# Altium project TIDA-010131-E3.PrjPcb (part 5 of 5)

## Sheet TIDA-010131-E3_Hardware.SchDoc
size 431 x 279 mm; Date: Not shown in title block; ApprovedBy: Not shown in title block; CheckedBy: Not shown in title block; Author: Not shown in title block; CompanyName: Not shown in title block; DrawnBy: Avinash N; Engineer: Not shown in title block; Organization: Not shown in title block; Address1: Not shown in title block; Address2: Not shown in title block; Address3: Not shown in title block; Address4: Not shown in title block; DocumentNumber: 1; Revision: Use project parameter SCH_Rev; SheetNumber: 9; SheetTotal: 9; PageSetup: Record=PageOptions¦CenterHorizontal=True¦CenterVertical=True¦PrintScale=1.00¦XCorrection=1.00¦YCorrection=1.00¦PrintKind=0¦BorderSize=5000000¦LeftOffset=0¦BottomOffset=0¦Orientation=2¦PaperLength=1000¦PaperWidth=1000¦Scale=100¦PaperSource=15¦PrintQuality=600¦MediaType=1¦DitherType=10¦PaperKind=Letter¦PrintScaleMode=1
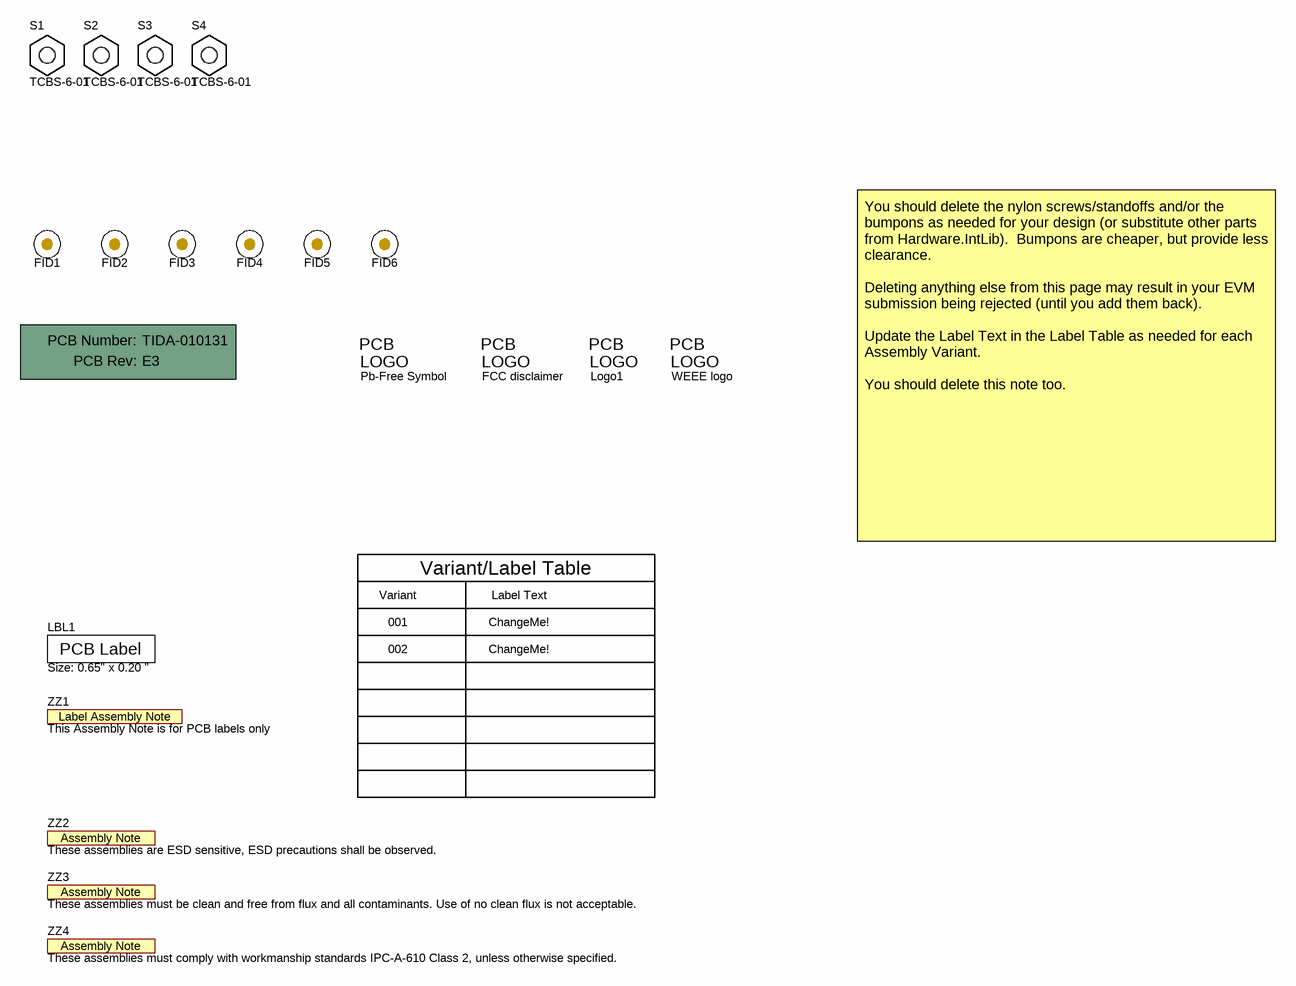
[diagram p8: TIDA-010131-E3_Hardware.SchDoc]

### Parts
!PCB1  Printed Circuit Board  (value not drawn)  (mechanical)
FID1  Fiducial  [Fiducial10-20]  (value not drawn)
FID2  Fiducial  [Fiducial10-20]  (value not drawn)
FID3  Fiducial  [Fiducial10-20]  (value not drawn)
FID4  Fiducial  [Fiducial10-20]  (value not drawn)
FID5  Fiducial  [Fiducial10-20]  (value not drawn)
FID6  Fiducial  [Fiducial10-20]  (value not drawn)
LBL1  Size: 0.65" x 0.20 "  [Label_650x200]
Logo1  ESD Susceptible  [ESD_Overlay_SMALL]  (value not drawn)  (no BOM)
Logo2  Pb-Free Symbol  [Pb-Free_Overlay_Small]  (no BOM)
Logo3  FCC disclaimer  [FCC_disclaimer]  (no BOM)
Logo4  WEEE logo  [WEEE_Minimum]  (no BOM)
S1  TCBS-6-01  [TCBS-6-01]
S2  TCBS-6-01  [TCBS-6-01]
S3  TCBS-6-01  [TCBS-6-01]
S4  TCBS-6-01  [TCBS-6-01]
ZZ1  This Assembly Note is for PCB labels only  [AssemblyNoteLabel]  (no BOM)
ZZ2  These assemblies are ESD sensitive, ESD precautions shall be observed.  [AssemblyNote]  (no BOM)
ZZ3  These assemblies must be clean and free from flux and all contaminants. Use of no clean flux is not acceptable.  [AssemblyNote]  (no BOM)
ZZ4  These assemblies must comply with workmanship standards IPC-A-610 Class 2, unless otherwise specified.  [AssemblyNote]  (no BOM)

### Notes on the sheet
- Variant
- Variant/Label Table
- Label Text
- You should delete the nylon screws/standoffs and/or the bumpons as needed for your design (or substitute other parts from Hardware.IntLib).  Bumpons are cheaper, but provide less clearance.
  Deleting anything else from this page may result in your EVM submission being rejected (until you add them back).
  Update the Label Text in the Label Table as needed for each Assembly Variant.
  You should delete this note too.
- 001
- 002
- ChangeMe!

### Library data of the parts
!PCB1 = PCB: Manufacturer: Any; PartNumber: TIDA-010131; SymbolCreator: a0412235
FID1-FID6 = Fiducial: Fiducial mark.  There is nothing to buy or mount.; SymbolCreator: codlsc
LBL1 = THT-14-423-10: Thermal Transfer Printable Labels, 0.650" W x 0.200" H - 10,000 per roll; Manufacturer: Brady; SymbolCreator: a0412235; CompType: Label
Logo1 = ESD_Susceptible: ESD Susceptible Symbol; SymbolCreator: a0412235
Logo2 = Pb-Free: SymbolCreator: a0412235
Logo3 = FCC_disclaimer: SymbolCreator: codlsc
Logo4 = CMP-0074769-1
S1-S4 = TCBS-6-01: HEX STANDOFF SPACER, 9.53 mm; Manufacturer: Richco Plastics; SymbolCreator: a0412235
ZZ1 = AssemblyNoteLabel: SymbolCreator: a0412235
ZZ2-ZZ4 = AssemblyNote: SymbolCreator: codlsc

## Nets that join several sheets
+2.5V: TIDA-010131-E3_LMK0482x _CLK_PWR (9 pins), TIDA-010131-E3_POWER SUPPLIES (7 pins)
+3.3V_LMX: TIDA-010131-E3_LMX2594R_1 (11 pins), TIDA-010131-E3_LMX2594R_2 (11 pins), TIDA-010131-E3_POWER SUPPLIES (7 pins)
+3.3V_LMXRF: TIDA-010131-E3_LMX2594R_1 (L11.1 L12.1 R87.1), TIDA-010131-E3_LMX2594R_2 (L13.1 L14.1 R120.1), TIDA-010131-E3_POWER SUPPLIES (7 pins)
+3.3V_VCO: TIDA-010131-E3_LMK0482x (5 pins), TIDA-010131-E3_POWER SUPPLIES (8 pins)
+3.3VLMK: TIDA-010131-E3_LMK0482x (8 pins), TIDA-010131-E3_LMK0482x _CLK_PWR (7 pins), TIDA-010131-E3_LMK00304_Buffer (14 pins), TIDA-010131-E3_LMX2594R_1 (C192.2 U23.8), TIDA-010131-E3_LMX2594R_2 (C193.2 U24.8), TIDA-010131-E3_POWER SUPPLIES (12 pins)
GND: TIDA-010131-E3_LMK0482x (98 pins), TIDA-010131-E3_LMK0482x _CLK_PWR (128 pins), TIDA-010131-E3_LMK00304_Buffer (28 pins), TIDA-010131-E3_LMX2594R_1 (63 pins), TIDA-010131-E3_LMX2594R_2 (63 pins), TIDA-010131-E3_USB (53 pins), TIDA-010131-E3_POWER SUPPLIES (99 pins)
Vcc1_VCO: TIDA-010131-E3_LMK0482x (U1.10 U1.33 U1.36), TIDA-010131-E3_LMK0482x _CLK_PWR (C34.1 C35.1 C36.1 L7.2)
Vcc2_CG1: TIDA-010131-E3_LMK0482x (U1.17), TIDA-010131-E3_LMK0482x _CLK_PWR (C26.1 L1.2)
Vcc3_SYSREF: TIDA-010131-E3_LMK0482x (U1.21), TIDA-010131-E3_LMK0482x _CLK_PWR (C28.1 L2.2)
Vcc4_CG2: TIDA-010131-E3_LMK0482x (U1.26), TIDA-010131-E3_LMK0482x _CLK_PWR (C31.1 L3.2)
Vcc7_OSCout: TIDA-010131-E3_LMK0482x (U1.39), TIDA-010131-E3_LMK0482x _CLK_PWR (C189.1 L6.2)
Vcc8_OSCin: TIDA-010131-E3_LMK0482x (U1.42), TIDA-010131-E3_LMK0482x _CLK_PWR (C190.2 L9.2)
Vcc9_CP2: TIDA-010131-E3_LMK0482x (U1.45), TIDA-010131-E3_LMK0482x _CLK_PWR (C191.2 L10.2)
Vcc10_PLL2: TIDA-010131-E3_LMK0482x (U1.47), TIDA-010131-E3_LMK0482x _CLK_PWR (7 pins)
Vcc11_CG3: TIDA-010131-E3_LMK0482x (U1.53), TIDA-010131-E3_LMK0482x _CLK_PWR (C32.1 L4.2)
Vcc12_CG0: TIDA-010131-E3_LMK0482x (U1.64), TIDA-010131-E3_LMK0482x _CLK_PWR (C33.1 L5.2)
VDDD33: TIDA-010131-E3_LMK0482x _CLK_PWR (5 pins), TIDA-010131-E3_LMK00304_Buffer (11 pins), TIDA-010131-E3_USB (29 pins), TIDA-010131-E3_POWER SUPPLIES (7 pins)
ACBUS1: TIDA-010131-E3_LMK0482x _CLK_PWR (J33.1 R209.1 U13.1), TIDA-010131-E3_USB (R341.1)
BUF_CLKIN_SEL0: TIDA-010131-E3_LMK0482x _CLK_PWR (R255.1 R256.1), TIDA-010131-E3_LMK00304_Buffer (J10.3 U16.13)
BUF_CLKIN_SEL1: TIDA-010131-E3_LMK0482x _CLK_PWR (R253.1 R254.1), TIDA-010131-E3_LMK00304_Buffer (J10.2 U16.16)
CLKin0_N: TIDA-010131-E3_LMK0482x (U1.38), TIDA-010131-E3_LMK0482x _CLK_PWR (C25.2)
CLKin0_P: TIDA-010131-E3_LMK0482x (U1.37), TIDA-010131-E3_LMK0482x _CLK_PWR (C24.2)
CLKin1_N: TIDA-010131-E3_LMK0482x (U1.35), TIDA-010131-E3_LMK0482x _CLK_PWR (C29.2 C30.2)
CLKin1_P: TIDA-010131-E3_LMK0482x (U1.34), TIDA-010131-E3_LMK0482x _CLK_PWR (C27.2)
CLKin_SEL0: TIDA-010131-E3_LMK0482x (U1.58), TIDA-010131-E3_LMK0482x _CLK_PWR (R78.1), TIDA-010131-E3_USB (R296.2)
CLKin_SEL1: TIDA-010131-E3_LMK0482x (U1.59), TIDA-010131-E3_LMK0482x _CLK_PWR (R77.1), TIDA-010131-E3_USB (R307.1)
CLKOUT_TYPE0: TIDA-010131-E3_LMK0482x _CLK_PWR (R257.1 R258.1), TIDA-010131-E3_LMK00304_Buffer (J10.4 U16.9)
CLKOUT_TYPE1: TIDA-010131-E3_LMK0482x _CLK_PWR (R251.1 R252.1), TIDA-010131-E3_LMK00304_Buffer (J10.1 U16.32)
DCLKout0_N: TIDA-010131-E3_LMK0482x (C6.1), TIDA-010131-E3_LMX2594R_1 (R275.2 R363.2)
DCLKout0_P: TIDA-010131-E3_LMK0482x (C5.1), TIDA-010131-E3_LMX2594R_1 (R274.2 R362.2)
DCLKout2_N: TIDA-010131-E3_LMK0482x (C16.1), TIDA-010131-E3_LMX2594R_2 (R279.2 R365.2)
DCLKout2_P: TIDA-010131-E3_LMK0482x (C15.1), TIDA-010131-E3_LMX2594R_2 (R278.2 R364.2)
F_CORECLK1_N: TIDA-010131-E3_LMK0482x (R70.2), TIDA-010131-E3_LMK0482x _CLK_PWR (J5.15)
F_CORECLK1_P: TIDA-010131-E3_LMK0482x (R182.2), TIDA-010131-E3_LMK0482x _CLK_PWR (J5.17)
F_CORECLK2_N: TIDA-010131-E3_LMK0482x (R183.2), TIDA-010131-E3_LMK0482x _CLK_PWR (J2.15)
F_CORECLK2_P: TIDA-010131-E3_LMK0482x (R184.2), TIDA-010131-E3_LMK0482x _CLK_PWR (J2.17)
F_LMK_CSb: TIDA-010131-E3_LMK0482x _CLK_PWR (U13.7), TIDA-010131-E3_USB (R187.2)
F_LMK_LMX_CLK: TIDA-010131-E3_LMK0482x _CLK_PWR (U13.12), TIDA-010131-E3_USB (R185.2)
F_LMK_LMX_DATA: TIDA-010131-E3_LMK0482x _CLK_PWR (U13.4), TIDA-010131-E3_USB (R186.2)
F_LMX1_SDO: TIDA-010131-E3_LMK0482x _CLK_PWR (J5.55), TIDA-010131-E3_USB (R189.2)
F_LMX2_SDO: TIDA-010131-E3_LMK0482x _CLK_PWR (J2.55), TIDA-010131-E3_USB (R225.2)
F_REFCLK1_N: TIDA-010131-E3_LMK0482x (R4.2), TIDA-010131-E3_LMK0482x _CLK_PWR (J5.7)
F_REFCLK1_P: TIDA-010131-E3_LMK0482x (R7.2), TIDA-010131-E3_LMK0482x _CLK_PWR (J5.9)
F_REFCLK2_N: TIDA-010131-E3_LMK0482x (R63.1), TIDA-010131-E3_LMK0482x _CLK_PWR (J2.7)
F_REFCLK2_P: TIDA-010131-E3_LMK0482x (R62.1), TIDA-010131-E3_LMK0482x _CLK_PWR (J2.9)
F_SYSREF1_N: TIDA-010131-E3_LMK0482x (R19.2), TIDA-010131-E3_LMK0482x _CLK_PWR (J5.23)
F_SYSREF1_P: TIDA-010131-E3_LMK0482x (R20.2), TIDA-010131-E3_LMK0482x _CLK_PWR (J5.25)
F_SYSREF2_N: TIDA-010131-E3_LMK0482x (R55.2), TIDA-010131-E3_LMK0482x _CLK_PWR (J2.23)
F_SYSREF2_P: TIDA-010131-E3_LMK0482x (R57.2), TIDA-010131-E3_LMK0482x _CLK_PWR (J2.25)
FMC_SPI_SCSb2: TIDA-010131-E3_LMK0482x _CLK_PWR (J5.60), TIDA-010131-E3_USB (R188.2)
FMC_SPI_SCSb4: TIDA-010131-E3_LMK0482x _CLK_PWR (J2.60), TIDA-010131-E3_USB (R206.2)
FREQ_DIV_RESET: TIDA-010131-E3_LMK0482x _CLK_PWR (R323.2 R324.2 U21.15), TIDA-010131-E3_USB (R335.1)
IOVLVL: TIDA-010131-E3_LMK0482x (U1.7), TIDA-010131-E3_USB (R210.2)
LMK04828_CSb: TIDA-010131-E3_LMK0482x (C18.2 U1.18), TIDA-010131-E3_USB (U18.9)
LMK_LMX_CLK: TIDA-010131-E3_LMK0482x (C20.2 U1.19), TIDA-010131-E3_LMX2594R_1 (U3.16), TIDA-010131-E3_LMX2594R_2 (U4.16), TIDA-010131-E3_USB (U18.4)
LMK_LMX_DATA: TIDA-010131-E3_LMK0482x (C21.2 U1.20), TIDA-010131-E3_LMX2594R_1 (U3.17), TIDA-010131-E3_LMX2594R_2 (U4.17), TIDA-010131-E3_USB (U18.7)
LMX1_CSb: TIDA-010131-E3_LMX2594R_1 (U3.24), TIDA-010131-E3_USB (U15.5 U19.4)
LMX1_REFN: TIDA-010131-E3_LMK00304_Buffer (R241.2 R247.2 R264.1), TIDA-010131-E3_LMX2594R_1 (R165.1)
LMX1_REFP: TIDA-010131-E3_LMK00304_Buffer (R240.2 R248.2 R262.1), TIDA-010131-E3_LMX2594R_1 (R103.2)
LMX1_SDO: TIDA-010131-E3_LMX2594R_1 (R102.2), TIDA-010131-E3_USB (R189.1 R218.2)
LMX2_CSb: TIDA-010131-E3_LMX2594R_2 (U4.24), TIDA-010131-E3_USB (U19.9)
LMX2_REFN: TIDA-010131-E3_LMK00304_Buffer (R243.2 R245.2 R268.1), TIDA-010131-E3_LMX2594R_2 (R168.1)
LMX2_REFP: TIDA-010131-E3_LMK00304_Buffer (R242.2 R246.2 R266.1), TIDA-010131-E3_LMX2594R_2 (R137.2)
LMX2_SDO: TIDA-010131-E3_LMX2594R_2 (R135.2), TIDA-010131-E3_USB (R219.2 R225.1)
OSCout_N: TIDA-010131-E3_LMK0482x (U1.41), TIDA-010131-E3_LMK00304_Buffer (R250.1 R265.2 R269.2)
OSCout_P: TIDA-010131-E3_LMK0482x (U1.40), TIDA-010131-E3_LMK00304_Buffer (R244.1 R263.2 R267.2)
PCLK1: TIDA-010131-E3_LMK0482x _CLK_PWR (J5.22), TIDA-010131-E3_POWER SUPPLIES (R259.2)
PCLK2: TIDA-010131-E3_LMK0482x _CLK_PWR (J2.22), TIDA-010131-E3_POWER SUPPLIES (R261.2)
RESET: TIDA-010131-E3_LMK0482x (C184.1 R35.2 R343.1 U1.5), TIDA-010131-E3_LMK0482x _CLK_PWR (U13.9), TIDA-010131-E3_USB (R311.1)
SCL: TIDA-010131-E3_LMK0482x (R43.1 U2.8), TIDA-010131-E3_LMK00304_Buffer (R321.1 U20.13), TIDA-010131-E3_USB (R172.1 R178.2)
SDA: TIDA-010131-E3_LMK0482x (R44.1 U2.7), TIDA-010131-E3_LMK00304_Buffer (R320.1 U20.12), TIDA-010131-E3_USB (R173.1 R212.2)
SDCLKout1_N: TIDA-010131-E3_LMK0482x (R27.1 R344.2), TIDA-010131-E3_LMX2594R_1 (R350.1 R358.2)
SDCLKout1_P: TIDA-010131-E3_LMK0482x (R25.1 R345.2), TIDA-010131-E3_LMX2594R_1 (R351.1 R359.2)
SDCLKout3_N: TIDA-010131-E3_LMK0482x (R42.1 R347.1), TIDA-010131-E3_LMX2594R_2 (R354.1 R360.2)
SDCLKout3_P: TIDA-010131-E3_LMK0482x (R41.1 R346.1), TIDA-010131-E3_LMX2594R_2 (R355.1 R361.2)
SDCLKout5_N: TIDA-010131-E3_LMK0482x (R10.2), TIDA-010131-E3_LMX2594R_2 (R281.1 U24.1)
SDCLKout5_P: TIDA-010131-E3_LMK0482x (R2.2), TIDA-010131-E3_LMX2594R_2 (R280.2 R281.2 U24.2)
SDCLKout11_N: TIDA-010131-E3_LMK0482x (R9.2), TIDA-010131-E3_LMX2594R_1 (R133.1 U23.1)
SDCLKout11_P: TIDA-010131-E3_LMK0482x (R1.2), TIDA-010131-E3_LMX2594R_1 (R101.2 R133.2 U23.2)
Status_LD1: TIDA-010131-E3_LMK0482x (R53.2 U1.31), TIDA-010131-E3_LMK0482x _CLK_PWR (R79.1)
Status_LD2: TIDA-010131-E3_LMK0482x (U1.48), TIDA-010131-E3_LMK0482x _CLK_PWR (R80.1)
SYNC: TIDA-010131-E3_LMK0482x (C185.1 R190.2 SYNC.1 U1.6), TIDA-010131-E3_LMK0482x _CLK_PWR (R200.2 R201.2 R202.2), TIDA-010131-E3_USB (R306.1)

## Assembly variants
001: not fitted C11 C22 C59 C92 C179 C184 C185 C186 C189 C190 C191 D7 D12 FID1 FID2 FID3 FID4 FID5 FID6 L19 L20 L23 L24 L26 L28 L29 L30 L32 R3 R6 R15 R16 R17 R18 R23 R24 R26 R34 R35 R37 R39 R40 R43 R44 R54 R56 R60 R61 R64 R65 R66 R67 R71 R72 R75 R76 R81 R84 R92 R98 R101 R104 R106 R108 R110 R111 R113 R114 R117 R125 R131 R134 R138 R139 R141 R143 R144 R146 R147 R167 R172 R173 R185 R186 R187 R188 R189 R190 R191 R195 R198 R199 R200 R201 R202 R206 R210 R211 R225 R259 R260 R261 R262 R263 R264 R265 R266 R267 R268 R269 R272 R273 R274 R275 R278 R279 R280 R284 R290 R296 R300 R311 R322 R327 R328 R329 R335 R336 R338 R340 R341 R343 R344 R345 R346 R347 R348 R349 R352 R353 R358 R359 R360 R361 R366 R367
